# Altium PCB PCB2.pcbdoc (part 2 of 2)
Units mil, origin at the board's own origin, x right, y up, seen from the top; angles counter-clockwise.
Board outline 1825.45 x 2756.54 mil, 4 copper layers (Top Layer, 3.3V, GND, Bottom Layer); 87 components, 95 nets, 418 pads, 113 vias.
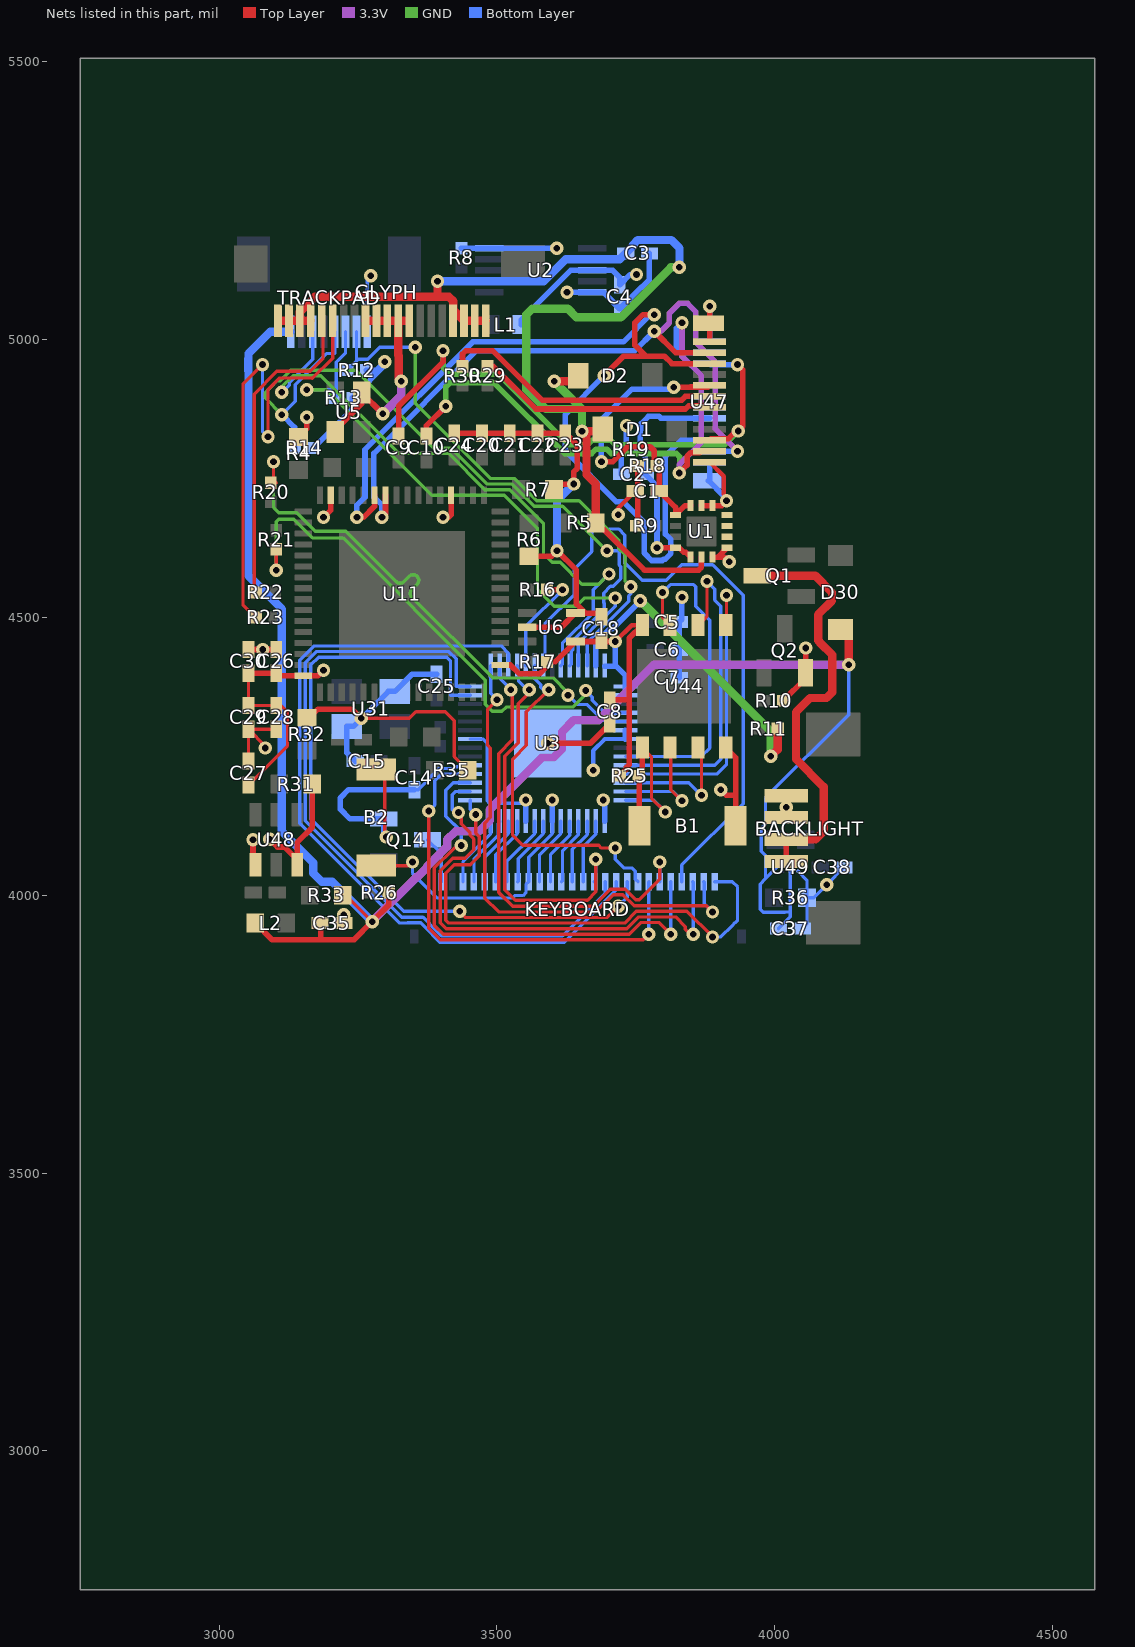
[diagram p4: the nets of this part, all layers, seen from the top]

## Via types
v1: diameter 24.02, hole 12.01, Top Layer to Bottom Layer, 113 vias

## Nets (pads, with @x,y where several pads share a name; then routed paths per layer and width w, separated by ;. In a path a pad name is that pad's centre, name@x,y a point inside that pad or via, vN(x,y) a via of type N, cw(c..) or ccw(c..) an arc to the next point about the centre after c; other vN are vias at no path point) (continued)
+3.3V: C4.2 C8.1 C18.1 C26.2 C27.2 C28.2 C29.2 C30.2 L1.2 R12.1 R13.1 R14.1 R16.2 R17.2 R25.1 R31.2 U1.3 U1.4 U2.8 U3.1 U3.10 U3.22 U3.33 U3.42 U3.43 U3.44 U3.48 U3.49 U6.4 U11.16 U11.34 U11.52 U11.63 U44.8 U48.3 | length 2677.7
  Top Layer w6: C27.2@3053.15,4198.54 3123.15,4268.54 3123.15,4330 3111.69,4341.46 C28.2@3103.15,4341.46 C29.2@3053.15,4341.46 C30.2@3053.15,4399.35
  Top Layer w8: v1(3713.15,4456.68) 3742.61,4486.14 U44.8@3761.8,4486.14
  Top Layer w10: C30.2@3053.15,4399.35 C26.2@3103.15,4399.35 3107.49,4395.01 U11.16@3151.96,4395.01 3178.16,4395.01 v1(3188.15,4405) ; v1(3091.11,4100.99) 3105.25,4086.85 3118.17,4086.85 U48.3@3140.55,4064.47 ; U48.3@3140.55,4054.76 U48.3@3140.55,4064.47 ; R31.2@3167.81,4200 3167.81,4122.02 3140.55,4094.76 U48.3@3140.55,4064.47 ; v1(3188.15,4680) 3201.17,4693.02 U11.63@3201.17,4719.81 ; v1(3403.15,4680) 3413.15,4680 3417.7,4684.55 U11.52@3417.7,4719.81 ; U11.34@3506.29,4414.7 3524.11,4414.7 3540.42,4398.39 3576.53,4398.39 3590.19,4412.04 R17.2@3590.19,4420 3604.81,4420 U6.4@3641.49,4456.68 v1(3713.15,4456.68) ; R16.2@3590.19,4550 v1(3618.15,4550) ; C8.1@3703.15,4351.46 3737.05,4351.46 3738.15,4350.36 ; R25.1@3721.11,4215 3733.07,4226.96 3733.07,4230.18 3738.15,4235.26 3738.15,4350.36 ; U44.8@3761.8,4486.14 3738.15,4462.5 3738.15,4350.36 ; U1.3@3887.84,4608.64 3897.68,4608.64 ; U1.4@3914.51,4625.47 3897.68,4608.64 ; v1(3918.15,4600) 3909.51,4608.64 3897.68,4608.64
  Bottom Layer w6: U3.22@3451.81,4281.25 3474.36,4281.25 3482.45,4273.16 3482.45,4170 3486.69,4165.76 3546.43,4165.76 v1(3552.2,4171.53) ; U3.33@3552.2,4413.15 3552.2,4484.06 v1(3618.15,4550)
  Bottom Layer w8: v1(3673.15,4225) 3673.15,4260 3694.4,4281.25 U3.49@3731.33,4281.25
  Bottom Layer w10: R14.1@3170.19,4805 3240.19,4875 R13.1@3240.19,4895 ; R13.1@3245.54,4900.43 3298.15,4953.03 v1(3298.15,4960) 3283.15,4945 R12.1@3265.19,4945 ; L1.2@3543.73,5026.97 3543.73,5035.58 3632.76,5124.61 U2.8@3671.61,5124.61 3708.54,5124.61 3721.17,5111.98 C4.2@3721.17,5098.44 3739.71,5116.98 v1(3751.17,5116.98) ; U3.10@3552.2,4133.61 v1(3552.2,4171.53) ; v1(3691.61,4171.53) 3693.93,4169.21 U3.1@3693.93,4133.61 ; U3.42@3693.94,4412.44 3714.36,4412.44 ; v1(3713.15,4456.68) 3713.15,4413.65 3714.36,4412.44 ; U3.49@3731.33,4281.25 U3.48@3731.33,4297 ; U3.44@3731.33,4359.99 U3.43@3731.33,4375.74 3731.33,4395.47 3714.36,4412.44
+5V: C35.2 C37.2 D30.2 L2.1 R26.2 R33.1 TRACKPAD.8 U49.B1 U49.C2 | length 3501
  Top Layer w6: R33.1@3222.81,4000 3228.15,4000 v1(3275.65,3952.5)
  Top Layer w10: L2.1@3065.59,3950.01 3095.6,3920 3182.97,3920 ; C35.2@3181.69,3950 3182.97,3948.71 3182.97,3920 ; R26.2@3305.19,4005 3305.19,3982.04 v1(3275.65,3952.5) 3243.15,3920 3182.97,3920
  Top Layer w15: D30.2@4118.15,4478.37 4133.15,4463.37 v1(4133.15,4415)
  3.3V w15: v1(3275.65,3952.5) 3357.66,4034.51 3358.71,4034.51 3373.64,4049.44 3373.64,4050.49 3410.67,4087.52 3410.67,4100.23 3425.6,4115.16 3467.71,4115.16 3487.21,4134.67 3487.21,4154.08 3581.02,4247.89 3602.14,4247.89 3617.07,4262.82 3617.07,4293.92 3638.15,4315 3683.15,4315 3783.15,4415 v1(4133.15,4415)
  Bottom Layer w6: C37.2@4006.69,3940 4028.15,3961.46 4028.15,3969.77 ; U49.C2@4014.37,4056.89 4012.92,4055.44 4009.26,4055.44 3983.29,4029.47 ; U49.B1@4028.15,4043.11 4028.15,3969.77 ; v1(4133.15,4415) 4133.15,4325 3983.29,4175.15 3983.29,4128.18 3975.86,4120.74 3975.86,4079.28 3983.29,4071.84 3983.29,4029.47 ; 3983.29,4029.47 3973.87,4020.05 3973.87,3974.89 3979.13,3969.62 4018.32,3969.62 4018.47,3969.77 4028.15,3969.77
  Bottom Layer w15: TRACKPAD.8@3128.56,5013.98 3092.13,5013.98 3053.15,4975 3053.15,4966.05 3052.66,4965.56 3052.66,4944.44 3053.15,4943.95 3053.15,4575 3113.15,4515 3113.15,4115 3169.67,4058.48 3169.67,4039.41 3184.6,4024.48 3203.67,4024.48 v1(3275.65,3952.5)
BACKLIGHT+: BACKLIGHT.3 BACKLIGHT.4 Q1.3 | length 775.8
  Top Layer w10: BACKLIGHT.4@4020.83,4060.95 BACKLIGHT.3@4020.83,4100.32
  Top Layer w15: Q1.3@3968.78,4575 4073.15,4575 4103.15,4545 4103.15,4530 4078.15,4505 4078.15,4458.45 4081.04,4455.56 4081.04,4455.07 4103.75,4432.35 4103.75,4365.61 4093.15,4355 4063.53,4355 4038.15,4329.62 4038.15,4245 4088.15,4195 4088.15,4115 4073.47,4100.32 BACKLIGHT.3@4020.83,4100.32
CAPS-: KEYBOARD.26 Q14.3 | length 86
  Bottom Layer w6: Q14.3@3375.12,4100 3399.69,4075.43 KEYBOARD.26@3399.69,4024.22
CC1: C1.2 R18.2 U1.10 U1.11 U47.A5 | length 570.2
  Top Layer w10: v1(3688.15,4780) 3708.15,4780 3735.22,4807.07 3776.08,4807.07 3783.15,4800 3783.15,4777.04 R18.2@3787.69,4772.5 3792.11,4768.08 C1.2@3792.11,4727.5 3821.79,4697.82 U1.11@3821.79,4684.53 3838.62,4701.36 U1.10@3848.47,4701.36 ; v1(3818.15,4914.09) 3848.12,4914.09 3848.66,4914.63 3879.94,4914.63 U47.A5@3882.73,4917.43
  Bottom Layer w10: v1(3688.15,4780) 3688.15,4855.8 3743.15,4910.8 3814.85,4910.8 v1(3818.15,4914.09)
CC2: C2.1 R19.2 U1.1 U1.14 U47.B5 | length 433.7
  Top Layer w10: v1(3788.15,4625.47) 3828.01,4625.47 3836.53,4616.95 3840.16,4616.95 U1.1@3848.47,4608.64
  Bottom Layer w10: v1(3788.15,4625.47) 3788.15,4736.46 C2.1@3767.11,4757.5 3767.11,4793.08 R19.2@3757.69,4802.5 3757.69,4836.19 3759.19,4837.69 3759.19,4848.18 3772.66,4861.65 3791.71,4861.65 3794.98,4858.38 U47.B5@3882.73,4858.38
EINK_OLED_USB_M: GLYPH.15 R23.1 | length 906.2
  Top Layer w6: R23.1@3066.11,4500 3043.15,4522.96 3043.15,4920 v1(3078.15,4955) ; v1(3088.15,4825) 3088.15,4910 3109.14,4930.99 3166.84,4930.99 3167.84,4930 3168.15,4930 3204.57,4966.42 GLYPH.15@3204.57,5033.82
  Bottom Layer w6: v1(3078.15,4955) 3078.15,4835 v1(3088.15,4825)
EINK_OLED_USB_P: GLYPH.16 R22.1 | length 577.5
  Top Layer w6: R22.1@3066.11,4545 3063.15,4547.96 3063.15,4901.97 3104.17,4942.99 3164.17,4942.99 3187.16,4965.99 3187.16,5031.55 GLYPH.16@3184.89,5033.82
GND: B1.1 B2.2 BACKLIGHT.1 BACKLIGHT.2 C1.1 C2.2 C3.2 C4.1 C5.2 C6.2 C7.2 C8.2 C14.1 C15.1 C18.2 C20.1 C21.1 C22.1 C23.1 C24.1 C25.2 C26.1 C27.1 C28.1 C29.1 C30.1 C35.1 C37.1 C38.2 GLYPH.8 GLYPH.9 GLYPH.10 GLYPH.11 GLYPH.12 Q2.2 Q14.2 R4.1 R6.2 R7.1 R8.1 R9.2 R10.1 R18.1 R19.1 R32.1 R35.2 R36.1 TRACKPAD.1 U1.8 U1.9 U2.5 U2.10 U3.19 U3.57 U5.2 U5.4 U6.2 U6.5 U31.2 U31.4 U44.4 U47.25 U47.26 U47.A1 U47.A12 U47.B1 U47.B12 U48.1 U49.A1 | length 4613.1
  Top Layer w6: C27.1@3053.15,4241.46 C29.1@3053.15,4298.54 ; v1(3083.15,4265) 3083.15,4268.54 C29.1@3053.15,4298.54 ; C28.1@3103.15,4298.54 C29.1@3053.15,4298.54 ; C35.1@3224.61,3950 v1(3224.61,3965) ; v1(3256.24,4318.33) 3342.65,4318.33 3354.34,4330.02 3407.3,4330.02 3423.16,4314.15 3423.16,4249.64 R35.2@3447.81,4225 ; B2.2@3299.63,4230.3 3298.15,4228.82 3298.15,4107.6 v1(3300.75,4105)
  Top Layer w8: v1(3718.15,4685) 3718.15,4696.46 C1.1@3749.19,4727.5 ; U47.A12@3882.73,4779.64 3908.26,4754.11 3908.26,4724.52 ccw(c3924.07,4724.52) 3913.15,4713.08 v1(3913.15,4710)
  Top Layer w10: C30.1@3053.15,4442.27 v1(3078.63,4442.27) C26.1@3103.15,4442.27 ; v1(3061.14,4100) 3061.14,4059.37 U48.1@3065.75,4054.76 ; R4.1@3143.15,4824.66 3158.15,4839.66 v1(3158.15,4860) ; R32.1@3158.15,4319.66 3162.81,4319.66 3178.15,4335 3239.57,4335 v1(3256.24,4318.33) ; U5.4@3209.42,4833.57 3209.42,4837.3 3256.66,4884.54 U5.2@3256.66,4904.43 v1(3294.62,4866.47) ; C24.1@3423.15,4831.46 C20.1@3473.15,4831.46 C21.1@3523.15,4831.46 C22.1@3573.15,4831.46 C23.1@3623.15,4831.46 3644.76,4809.85 3644.76,4768.44 3638.15,4761.82 v1(3638.15,4740) 3612.81,4740 R7.1@3602.81,4730 ; U6.2@3554.87,4482.27 3615.9,4482.27 U6.5@3641.49,4507.86 3659.43,4507.86 ; R6.2@3558.15,4610.34 3598.49,4610.34 v1(3608.15,4620) 3643.15,4585 3643.15,4524.15 3659.43,4507.86 ; v1(3591.58,4273.38) 3667.99,4273.38 C8.2@3703.15,4308.54 ; C18.2@3688.15,4501.46 3681.74,4507.86 3659.43,4507.86 ; R9.2@3751.11,4665 3753.61,4667.5 R18.1@3753.61,4772.5 ; U1.9@3868.15,4701.36 U1.8@3887.84,4701.36 3904.51,4701.36 v1(3913.15,4710) ; U47.A1@3882.7,4996.14 3882.7,5027.64 3880.73,5029.61 3883.15,5032.02 v1(3883.15,5060) ; v1(3903.15,4190) 3913.15,4180 3929.76,4180 ; U44.4@3911.8,4265.65 3929.76,4247.69 3929.76,4180 ; B1.1@3929.76,4125 3929.76,4180 ; R10.1@4015.19,4350 4055.55,4390.36 Q2.2@4055.55,4400.63 v1(4055.55,4445) ; BACKLIGHT.2@4020.83,4139.69 v1(4020.83,4158.21) BACKLIGHT.1@4020.83,4179.06
  Top Layer w15: GLYPH.12@3264.31,5033.82 GLYPH.11@3283.31,5033.82 GLYPH.10@3303,5033.82 GLYPH.9@3322.68,5033.82 ; v1(3328.15,4925) 3323.64,4929.51 3323.64,4970.56 3322.68,4971.52 GLYPH.9@3322.68,5033.82 ; GLYPH.8@3341.67,5033.82 GLYPH.9@3322.68,5033.82
  3.3V w15: v1(3294.62,4866.47) 3328.15,4900 v1(3328.15,4925)
  Bottom Layer w6: TRACKPAD.1@3267.05,5013.98 3267.05,5108.9 v1(3273.15,5115) ; C14.1@3351.61,4190.07 3358.24,4190.07 3396.44,4228.28 3423.53,4228.28 3426.44,4231.18 3448.99,4231.18 U3.19@3451.81,4234.01 ; U49.A1@4041.93,4043.11 4058.05,4026.99 R36.1@4058.05,3995.62 ; C37.1@4049.61,3940 4058.05,3948.44 R36.1@4058.05,3995.62 ; C38.2@4124.61,4050 v1(4093.43,4018.82) 4070.22,3995.62 R36.1@4058.05,3995.62
  Bottom Layer w10: C15.1@3245.15,4241.53 3229.92,4256.77 U31.2@3229.92,4303.81 3241.73,4303.81 v1(3256.24,4318.33) 3304.72,4366.8 U31.4@3316.53,4366.8 3347.72,4397.99 C25.2@3391.61,4397.99 ; v1(3300.75,4105) 3296.38,4109.37 Q14.2@3296.38,4137.4 3235.75,4137.4 3218.15,4155 3218.15,4175 3233.22,4190.07 C14.1@3351.61,4190.07 ; R8.1@3436.17,5164.02 3486.53,5164.02 3486.99,5164.41 v1(3607.72,5164.41) ; v1(3626.17,5085.23) U2.10@3671.61,5085.23 3691.46,5085.23 C4.1@3721.17,5055.52 3759.64,5093.99 3760.69,5093.99 3774.61,5107.9 C3.2@3774.61,5155 ; C2.2@3724.19,4757.5 3724.19,4801.92 R19.1@3723.61,4802.5 3733.15,4812.04 v1(3733.15,4845) ; C7.2@3828.07,4391.53 C6.2@3828.07,4441.53 C5.2@3828.07,4491.53 3833.07,4496.53 v1(3833.07,4536.53) ; U47.B1@3882.73,4779.64 3882.7,4748.11 3880.73,4746.14 3908.31,4718.56 ccw(c3924.04,4724.49) 3913.15,4711.68 v1(3913.15,4710) ; U47.B12@3882.7,4996.14 3882.7,5026.49 3882.7,5059.55 v1(3883.15,5060)
  Bottom Layer w15: v1(3608.15,4620) 3608.15,4710 v1(3638.15,4740)
INT_USBC_CTRL: U1.5
KBRD0: KEYBOARD.1 U3.15 | length 937.3
  Top Layer w6: v1(3461.72,4145.22) 3461.72,4111.96 3468.16,4105.51 3468.16,4070.85 3452.3,4054.98 3423.15,4055 3408.15,4040 3408.15,3955 3413.15,3950 3729.84,3950.02 3750.84,3971.02 3842.12,3971.02 v1(3888.15,3925)
  Bottom Layer w6: U3.15@3451.81,4171.02 3452.03,4170.81 3452.03,4154.91 v1(3461.72,4145.22) ; v1(3888.15,3925) 3903.15,3925 3923.18,3945.03 3923.18,3945.26 3928.45,3950.52 3928.67,3950.52 3933.15,3955 3933.15,4015 3923.94,4024.21 KEYBOARD.1@3891.81,4024.21
KBRD1: KEYBOARD.2 U3.29 | length 942.9
  Top Layer w6: v1(3500.26,4352.1) 3483.15,4334.99 3483.15,4270 3488.15,4265 3488.15,4140 3478.15,4130 3478.15,3995 3503.15,3970 3678.15,3970 3709.14,4000.99 3726.84,4000.99 3746.8,3981.04 3877.11,3981.04 v1(3888.15,3970)
  Bottom Layer w6: U3.29@3489.2,4413.15 3489.2,4363.16 v1(3500.26,4352.1) ; KEYBOARD.2@3872.13,4024.21 3873.15,4023.19 3873.15,3985 v1(3888.15,3970)
KBRD2: KEYBOARD.3 U3.16 | length 902.8
  Top Layer w6: v1(3431.04,4149.01) 3436.04,4144.01 3436.04,4128.47 3451.7,4112.81 3451.7,4107.81 3458.15,4101.37 3458.15,4081.97 3442.98,4066.81 3420.79,4066.81 3398.13,4044.15 3398.13,3950.85 3409,3939.98 3733.97,3939.98 3754.99,3961.01 3821.83,3961.01 3839.14,3943.7 3839.14,3939.01 3846.41,3931.74 3851.41,3931.74 v1(3853.15,3930)
  Bottom Layer w6: v1(3431.04,4149.01) 3428.57,4146.54 3426.61,4146.54 3419.64,4153.51 3419.64,4180.76 3425.64,4186.76 U3.16@3451.81,4186.76 ; KEYBOARD.3@3852.44,4024.21 3853.15,4023.5 v1(3853.15,3930)
KBRD3: KEYBOARD.4 U3.35 | length 1215.3
  Bottom Layer w6: U3.35@3583.69,4413.15 3586.52,4415.98 3586.52,4488.37 3639.14,4540.99 3639.14,4586.99 3670.64,4618.49 3670.64,4655 3674.88,4659.24 3718.91,4659.24 3730.13,4648.02 3730.13,4598.4 3761.54,4566.98 3804.75,4566.98 3832.77,4595 3888.15,4595 3943.15,4540 3943.15,4165 3832.76,4054.61 KEYBOARD.4@3832.76,4024.21
KBRD4: KEYBOARD.5 U3.17 | length 873.8
  Top Layer w6: v1(3436.16,4089.67) 3431.49,4085 3423.01,4085 3387.53,4049.52 3387.53,3945.62 3403.13,3930.02 3738.16,3930.02 3759.14,3950.99 3792.16,3950.99 v1(3813.15,3930)
  Bottom Layer w6: v1(3436.16,4089.67) 3436.16,4115 3423.15,4128.02 3422.34,4128.02 3408.15,4142.21 3408.15,4189.43 3421.23,4202.51 U3.17@3451.81,4202.51 ; KEYBOARD.5@3813.07,4024.21 3813.07,3930.08 v1(3813.15,3930)
KBRD5: KEYBOARD.6 U3.30 | length 831
  Top Layer w6: v1(3524.78,4370.01) 3527.61,4367.19 3527.61,4279.46 3503.15,4255 3503.15,4005 3528.15,3980 3673.15,3980 3704.16,4011.01 3730.99,4011.01 3750.07,3991.93 3756.07,3991.93 3793.15,4029 v1(3793.15,4060)
  Bottom Layer w6: U3.30@3504.95,4413.15 3504.95,4390.61 3524.78,4370.78 v1(3524.78,4370.01) ; v1(3793.15,4060) 3793.39,4059.76 KEYBOARD.6@3793.39,4024.21
KBRD6: KEYBOARD.7 U3.18 | length 841.2
  Top Layer w6: v1(3377.51,4151.77) 3377.51,3940.63 3398.15,3920 3763.15,3920 v1(3773.15,3930)
  Bottom Layer w6: v1(3377.51,4151.77) 3388.15,4162.41 3388.15,4205.82 3400.59,4218.26 U3.18@3451.81,4218.26 ; v1(3773.15,3930) 3773.15,4023.66 KEYBOARD.7@3773.7,4024.21
KBRD7: KEYBOARD.8 U3.34 | length 628.7
  Top Layer w6: v1(3593.15,4370) 3553.15,4330 3553.15,4270 3528.15,4245 3528.15,4108.45 3546.6,4090 3683.15,4090 3688.15,4085 v1(3713.15,4085)
  Bottom Layer w6: U3.34@3567.94,4413.15 3567.94,4389.89 3579.14,4378.7 3579.14,4374.41 3583.55,4370 v1(3593.15,4370) ; v1(3713.15,4085) 3713.15,4065.08 3729.29,4048.94 3743.96,4048.94 3749.22,4043.68 3749.22,4029.01 KEYBOARD.8@3754.02,4024.21
KBRD8: KEYBOARD.9 U3.27 | length 1319.4
  Top Layer w6: v1(3433.15,3971.01) 3444.16,3960 3698.15,3960 v1(3718.15,3980)
  Bottom Layer w6: v1(3433.15,3971.01) 3332.14,3971.01 3165.16,4137.99 3165.16,4414.52 3179.24,4428.6 3409.54,4428.6 3416.61,4421.53 3416.61,4359.99 U3.27@3451.81,4359.99 ; v1(3718.15,3980) 3734.33,3996.18 KEYBOARD.9@3734.33,4024.21
KBRD9: KEYBOARD.10 U3.31 | length 1420.2
  Bottom Layer w6: U3.31@3520.7,4413.15 3520.7,4435.7 3507.77,4448.64 3170.94,4448.64 3145.12,4422.82 3145.12,4129.69 3324.82,3950 3339.34,3950 3339.87,3950.52 3363.06,3950.52 3368.32,3945.26 3368.32,3945 3398.32,3915 3620.11,3915 3714.65,4009.54 KEYBOARD.10@3714.65,4024.21
KBRD10: KEYBOARD.11 U3.28 | length 1322.6
  Bottom Layer w6: U3.28@3451.81,4375.74 3426.82,4375.74 3426.63,4375.93 3426.63,4425.68 3413.69,4438.62 3175.09,4438.62 3155.14,4418.67 3155.14,4133.84 3328.42,3960.56 3367.18,3960.56 3378.34,3949.41 3378.34,3949.15 3400.32,3927.17 3618.11,3927.17 3694.96,4004.02 KEYBOARD.11@3694.96,4024.21
KBRD11: KEYBOARD.12 U3.32 | length 711.4
  Top Layer w6: v1(3558.15,4370) 3558.15,4364.53 3538.62,4345 3538.62,4274.46 3514.16,4250 3514.16,4010.29 3533.44,3991.02 3663.15,3991.02 3678.15,4006.02 v1(3678.15,4065)
  Bottom Layer w6: U3.32@3536.45,4413.15 3538.81,4410.79 3538.81,4385.67 3554.48,4370 v1(3558.15,4370) ; KEYBOARD.12@3675.26,4024.22 3678.15,4027.11 v1(3678.15,4065)
KBRD12: KEYBOARD.13 U3.2 | length 118.8
  Bottom Layer w6: KEYBOARD.13@3655.59,4024.22 3655.59,4087.44 3678.18,4110.04 U3.2@3678.18,4133.61
KBRD13: KEYBOARD.14 U3.3 | length 120.4
  Bottom Layer w6: KEYBOARD.14@3635.91,4024.22 3635.91,4082.76 3662.43,4109.29 U3.3@3662.43,4133.61
KBRD14: KEYBOARD.15 U3.4 | length 122
  Bottom Layer w6: KEYBOARD.15@3616.22,4024.22 3618.15,4026.15 3618.15,4080 3646.68,4108.54 U3.4@3646.68,4133.61
KBRD15: KEYBOARD.16 U3.5 | length 123.6
  Bottom Layer w6: KEYBOARD.16@3596.54,4024.22 3596.54,4073.39 3630.94,4107.8 U3.5@3630.94,4133.61
KBRD16: KEYBOARD.17 U3.6 | length 125.3
  Bottom Layer w6: KEYBOARD.17@3576.85,4024.22 3576.85,4072.72 3615.19,4111.07 U3.6@3615.19,4133.61
KBRD17: KEYBOARD.20 U3.9 | length 130.2
  Bottom Layer w6: KEYBOARD.20@3517.8,4024.22 3517.8,4060.91 3567.94,4111.06 U3.9@3567.94,4133.61
KBRD18: KEYBOARD.19 U3.8 | length 128.5
  Bottom Layer w6: KEYBOARD.19@3537.48,4024.22 3538.43,4025.17 3538.43,4065.8 3583.69,4111.07 U3.8@3583.69,4133.61
KBRD19: B2.1 KEYBOARD.18 U3.7 | length 500.9
  Top Layer w6: B2.1@3283.15,4053.39 3341.54,4053.39 v1(3348.15,4060)
  Bottom Layer w6: v1(3348.15,4060) 3348.15,4040 3393.15,3995 3527.95,3995 3532.44,3999.49 3547.11,3999.49 3552.37,4004.75 3552.37,4019.42 KEYBOARD.18@3557.17,4024.22 3557.17,4068.79 3599.44,4111.07 U3.7@3599.44,4133.61
  Bottom Layer w10: U3.7@3599.44,4133.61 v1(3599.44,4171.53)
KBRD20: KEYBOARD.21 U3.11 | length 125.3
  Bottom Layer w6: KEYBOARD.21@3498.11,4024.22 3498.11,4072.72 3536.45,4111.07 U3.11@3536.45,4133.61
KBRD21: KEYBOARD.22 U3.12 | length 126.9
  Bottom Layer w6: KEYBOARD.22@3478.43,4024.22 3478.43,4068.79 3520.7,4111.07 U3.12@3520.7,4133.61
KBRD22: KEYBOARD.23 U3.13 | length 128.5
  Bottom Layer w6: KEYBOARD.23@3458.74,4024.22 3458.74,4064.85 3502.12,4108.24 3502.12,4128.98 3504.95,4131.81 U3.13@3504.95,4133.61
KBRD23: KEYBOARD.24 U3.14 | length 130.2
  Bottom Layer w6: KEYBOARD.24@3439.06,4024.22 3439.06,4060.91 3489.2,4111.06 U3.14@3489.2,4133.61
KBRD_CTRL: R11.1 U3.41 | length 584.8
  Top Layer w15: v1(3993.15,4250) 4005.19,4262.04 R11.1@4005.19,4300
  GND w15: v1(3758.15,4530) 3993.15,4295 v1(3993.15,4250)
  Bottom Layer w10: U3.41@3678.18,4413.15 3678.18,4450.04 3690.16,4462.01 3690.16,4466.21 3703.62,4479.68 3707.82,4479.68 v1(3758.15,4530)
KBRDUSB_M: R21.1 U3.46 | length 964.6
  Top Layer w6: v1(3103.15,4585) R21.1@3103.15,4622.96
  GND w6: v1(3103.15,4585) 3103.15,4672.26 3107.39,4676.5 3134.68,4676.5 3168.18,4643 3223.18,4643 3479.27,4386.91 3479.27,4343.41 3491.57,4331.11 3508.96,4331.11 3516.65,4338.8 3636.64,4338.8 3659.86,4362.03 v1(3659.86,4368.51)
  Bottom Layer w6: v1(3659.86,4368.51) 3671.89,4356.48 3671.89,4350.54 3695.81,4326.63 3701.81,4326.63 3703.68,4328.5 U3.46@3731.33,4328.5
KBRDUSB_P: R20.1 U3.47 | length 967.6
  Top Layer w6: v1(3098.15,4780) 3098.15,4747.04 R20.1@3103.15,4742.04
  GND w6: v1(3098.15,4780) 3098.15,4697.74 3107.39,4688.5 3139.65,4688.5 3173.15,4655 3228.15,4655 3318.71,4564.44 ccw(c3325.78,4571.51) 3332.85,4564.44 3342.35,4573.93 cw(c3349.42,4566.86) 3356.49,4559.79 3347,4550.29 ccw(c3354.07,4543.22) 3347,4536.15 3492.14,4391.01 3601.83,4391.01 3627.94,4364.89 v1(3627.94,4359.79)
  Bottom Layer w6: v1(3627.94,4359.79) 3644.34,4343.39 3662.07,4343.39 3690.83,4314.63 3701.81,4314.63 3703.68,4312.75 U3.47@3731.33,4312.75
QSPI_SCLK: U3.52 U44.6 | length 592.3
  Top Layer w6: U44.6@3861.8,4486.14 3878.15,4502.5 v1(3878.15,4565)
  Bottom Layer w6: U3.52@3731.33,4234.01 3892.16,4234.01 3903.15,4245 3903.13,4520.33 3892.16,4531.3 3892.16,4550.99 v1(3878.15,4565)
QSPI_SD0: U3.53 U44.5 | length 548.2
  Top Layer w6: U44.5@3911.8,4486.14 3913.15,4487.5 v1(3913.15,4540)
  Bottom Layer w6: U3.53@3731.33,4218.26 3896.41,4218.26 3913.15,4235 v1(3913.15,4540)
QSPI_SD1: U3.55 U44.2 | length 213.3
  Top Layer w6: U44.2@3811.8,4265.65 3813.15,4264.3 3813.15,4190 v1(3833.15,4170)
  Bottom Layer w6: U3.55@3731.33,4186.76 3816.39,4186.76 v1(3833.15,4170)
QSPI_SD2: U3.54 U44.3 | length 234.4
  Top Layer w6: U44.3@3861.8,4265.65 3868.15,4259.3 v1(3868.15,4180)
  Bottom Layer w6: U3.54@3731.33,4202.51 3845.64,4202.51 v1(3868.15,4180)
QSPI_SD3: U3.51 U44.7 | length 590.6
  Top Layer w6: v1(3798.15,4545) 3798.15,4499.79 U44.7@3811.8,4486.14
  Bottom Layer w6: U3.51@3731.33,4249.76 3867.91,4249.76 3883.15,4265 3883.15,4495 3858.15,4520 3858.15,4555 3853.91,4559.24 3812.39,4559.24 v1(3798.15,4545)
QSPI_SS: B1.2 R25.2 U3.56 U44.1 | length 357.3
  Top Layer w6: U44.1@3761.8,4265.65 3778.15,4249.3 3778.15,4175 v1(3803.15,4150)
  Top Layer w10: B1.2@3756.54,4125 3756.54,4213.65 R25.2@3755.19,4215 3761.8,4221.61 U44.1@3761.8,4265.65
  Bottom Layer w6: U3.56@3731.33,4171.02 3782.13,4171.02 v1(3803.15,4150)
SCL_USBC_CTRL: U1.6
SDA_USBC_CTRL: U1.7
SSRXN1: U11.59 U47.A3 U47.B3 | length 1871.7
  Top Layer w10: v1(3248.15,4680) 3259.91,4680 3279.91,4700 U11.59@3279.91,4719.81 ; v1(3693.15,4935) 3728.15,4970 3768.15,4970 ; v1(3783.15,5044.95) 3763.1,5044.95 3748.15,5030 3748.15,4990 3768.15,4970 ; U47.A3@3882.73,4956.8 3814.86,4956.8 3801.65,4970 3768.15,4970
  Bottom Layer w10: v1(3248.15,4680) 3248.15,4702.01 3262.65,4716.51 3262.65,4801.98 3456.66,4996 3727.57,4996 3776.52,5044.95 v1(3783.15,5044.95) ; v1(3693.15,4935) 3623.15,4865 3623.15,4800 3715.16,4707.99 3727.67,4707.99 3765.16,4670.51 3765.16,4615.95 3778.62,4602.48 3797.67,4602.48 3800.19,4605 3803.15,4605 3813.15,4615 3813.15,4640 3803.15,4650 3803.15,4790 3832.15,4819.01 U47.B3@3882.73,4819.01
SSRXP1: U11.58 U47.A2 U47.B2 | length 1318.9
  Top Layer w10: v1(3293.15,4680) 3299.59,4686.44 U11.58@3299.59,4719.81 ; v1(3783.15,5014.95) 3821.61,4976.48 U47.A2@3882.73,4976.48
  3.3V w10: v1(3783.15,5014.95) 3795.1,5014.95 3810.16,5030 3810.16,5047.01 3828.15,5065 3843.15,5065 3858.15,5050 3858.15,4995 3893.15,4960 3893.15,4839.31 v1(3933.15,4799.31)
  Bottom Layer w10: v1(3293.15,4680) 3293.15,4702.01 3278.65,4716.51 3278.65,4795.36 3463.29,4980 3748.2,4980 v1(3783.15,5014.95) ; U47.B2@3882.73,4799.31 v1(3933.15,4799.31)
SSTXN1: C9.1 U47.A10 U47.B10 | length 1059
  Top Layer w10: C9.1@3323.15,4826.46 3323.15,4880 3403.15,4960 v1(3403.15,4980) ; U47.A10@3882.73,4819.01 3885.52,4821.8 3916.81,4821.8 3930.43,4835.42 v1(3934.52,4835.42) 3942.69,4843.59 3942.69,4945.46 v1(3933.15,4955)
  GND w10: v1(3403.15,4980) 3403.15,4950.07 3415.22,4938 3501.79,4938 3628.79,4811 3664,4811 3672,4818.99 3704.3,4818.99 3712.29,4811 3910.1,4811 v1(3934.52,4835.42)
  Bottom Layer w10: U47.B10@3882.73,4956.8 3884.53,4955 v1(3933.15,4955)
SSTXP1: C10.1 U47.A11 U47.B11 | length 1111.5
  Top Layer w10: C10.1@3373.15,4826.46 3373.15,4845 v1(3408.15,4880) ; v1(3828.15,4760) 3842.22,4774.07 3842.22,4790.09 3848.66,4796.52 3864.67,4796.52 3867.46,4799.31 U47.A11@3882.73,4799.31
  3.3V w10: v1(3828.15,4760) 3828.15,4775 3868.15,4815 3868.15,4935 3833.15,4970 v1(3833.15,5030)
  GND w10: v1(3408.15,4880) 3408.15,4914.93 3415.22,4922 3495.16,4922 3622.16,4795 3670.63,4795 3678.62,4802.99 3697.67,4802.99 3705.66,4795 3823.15,4795 3829.01,4789.14 3829.01,4760.86 v1(3828.15,4760)
  Bottom Layer w10: v1(3833.15,5030) 3823.15,5020 3823.15,4985 3831.66,4976.48 U47.B11@3882.73,4976.48
TOUCHPAD_ID: TRACKPAD.6 U3.37 | length 1139.5
  GND w6: v1(3113.15,4905) 3113.15,4915 3133.15,4935 3183.15,4935 3323.15,4795 3413.15,4795 3478.15,4730 3523.15,4730 3583.91,4669.24 3583.91,4614.24 3588.15,4610 3588.46,4610 3599.45,4599.01 3614.14,4599.01 3653.15,4560 3683.46,4560 v1(3701.71,4578.24)
  Bottom Layer w6: v1(3113.15,4905) 3126.09,4917.94 3126.09,4922.11 3168.62,4964.63 TRACKPAD.6@3168.62,5013.98 ; U3.37@3615.19,4413.15 3618.02,4415.98 3618.02,4453.56 3673.15,4508.68 3673.15,4549.69 v1(3701.71,4578.24) 3700.65,4579.3 v1@3700.65,4582.5
TOUCHPAD_INT: R12.2 TRACKPAD.2 U3.40 | length 1028.6
  GND w6: v1(3353.16,4986.3) 3353.16,4885.02 3488.15,4750.03 3531.45,4750.03 3571.46,4710.02 3647.82,4710.02 3719.14,4638.7 3719.14,4624.01 3730.65,4612.5 3730.65,4565 v1(3740.65,4555)
  Bottom Layer w6: R12.2@3231.11,4945 3245.07,4958.96 3245.07,4959.35 3250.33,4964.61 3267.45,4964.61 3272.84,4970 3273.15,4970 3289.45,4986.3 v1(3353.16,4986.3) ; 3247.36,4961.64 TRACKPAD.2@3247.36,5013.98 ; U3.40@3662.43,4413.15 3662.43,4455.48 3698.65,4491.69 3699.84,4491.69 3737.16,4529.01 3737.16,4538.7 3740.65,4542.19 v1(3740.65,4555)
TOUCHPAD_SCL: R13.2 TRACKPAD.3 U3.39 | length 1121.3
  GND w6: v1(3158.15,4910) 3193.15,4910 3383.15,4720 3513.15,4720 3573.15,4660 3573.15,4550 3603.15,4520 3643.15,4520 3658.15,4535 v1(3713.15,4535)
  Bottom Layer w6: v1(3158.15,4910) 3201.89,4910 3203.78,4908.11 ; R13.2@3206.11,4895 3210.99,4899.88 3210.99,4900.9 3210.99,4959.35 3227.68,4976.04 TRACKPAD.3@3227.68,5013.98 ; U3.39@3646.68,4413.15 3646.68,4453.89 3694.5,4501.71 3694.85,4501.71 3713.15,4520 v1(3713.15,4535)
  Bottom Layer w10: 3203.78,4908.11 R13.2@3210.99,4900.9
TOUCHPAD_SDA: R14.2 TRACKPAD.4 U3.38 | length 1360.9
  GND w6: v1(3113.15,4865) 3083.15,4895 3083.15,4904.69 3104.45,4925.99 3109.98,4925.99 3129,4945.02 3245.78,4945 3385.76,4805.02 3417.3,4805.02 3482.3,4740.02 3527.3,4740.02 3567.31,4700 3618.15,4700 v1(3698.15,4620)
  Bottom Layer w6: v1(3113.15,4865) 3137.16,4889.01 3137.16,4918.7 3193.3,4974.84 3207.99,4974.84 TRACKPAD.4@3207.99,5013.98 ; U3.38@3630.94,4413.15 3633.76,4415.97 3633.76,4438.53 3636.67,4441.43 3636.67,4458.04 3693.15,4514.52 3693.15,4525.31 3692.16,4526.3 3692.16,4543.7 3704.45,4555.99 3709.14,4555.99 3723.15,4570 3723.15,4591.22 3720.12,4594.25 3720.12,4623.03 3717.09,4620 v1(3698.15,4620)
  Bottom Layer w10: v1(3113.15,4865) 3136.11,4842.04 R14.2@3136.11,4805
USB_UP+: R30.2 U47.A6 U47.B6 | length 435
  Top Layer w10: 3483.15,4952.04 3493.15,4952.04 3570.09,4875.1 3839.3,4875.1 3845.02,4880.83 3879.9,4880.83 3882.7,4878.03
USB_UP-: R29.2 U47.A7 U47.B7 | length 508.6
  Top Layer w10: 3438.15,4952.04 3438.15,4974 3444.15,4980 3492.49,4980 3581.39,4891.1 3832.67,4891.1 3839.29,4897.72 3882.7,4897.72
VBUS: C3.1 D1.1 D2.1 GLYPH.1 GLYPH.2 GLYPH.3 GLYPH.4 GLYPH.17 GLYPH.18 GLYPH.19 GLYPH.20 R5.1 U1.2 U2.2 U2.7 | length 2176.1
  Top Layer w10: R5.1@3677.81,4670 3680.66,4670 3765.66,4585 3863.15,4585 3868.15,4590 U1.2@3868.15,4608.64
  Top Layer w15: GLYPH.20@3106.15,5033.82 GLYPH.19@3125.83,5033.82 GLYPH.18@3145.52,5033.82 ; GLYPH.17@3164.51,5033.82 GLYPH.18@3145.52,5033.82 ; v1(3393.15,5104.92) 3393.15,5077.83 3394.15,5076.83 ; GLYPH.1@3480.16,5033.82 GLYPH.2@3460.48,5033.82 GLYPH.3@3440.79,5033.82 3421.79,5052.82 3421.79,5068.93 3413.89,5076.83 3394.15,5076.83 ; v1(3603.15,4925) 3636.52,4925 D2.1@3646.52,4935 ; R5.1@3677.81,4670 3678.15,4670.34 3678.15,4740 3661.28,4756.87 3661.28,4826.87 v1(3653.15,4835) 3686.76,4835 D1.1@3690.55,4838.79 ; GLYPH.18@3145.52,5033.82 3145.52,5049.94 3172.41,5076.83 3394.15,5076.83
  GND w15: v1(3603.15,4925) 3653.15,4875 ; v1(3653.15,4835) 3653.15,4875 ; v1(3828.15,5130) 3813.15,5130 3723.15,5040 3643.15,5040 3627.54,5055.61 3563.75,5055.61 3553.15,5045 3553.15,4910 3588.15,4875 3653.15,4875
  Bottom Layer w15: v1(3393.15,5104.92) U2.2@3486.57,5104.92 3584.29,5104.92 3623.67,5144.3 U2.7@3671.61,5144.3 3720.99,5144.3 C3.1@3731.69,5155 3745.57,5168.88 3745.57,5171.22 3753.47,5179.11 3814.03,5179.11 3828.75,5164.39 3828.75,5130.61 v1(3828.15,5130)
pads on no net: BACKLIGHT.5 BACKLIGHT.6 GLYPH.5 GLYPH.6 GLYPH.7 GLYPH.13 GLYPH.14 GLYPH.21 GLYPH.22 KEYBOARD.27 KEYBOARD.28 TRACKPAD.5 TRACKPAD.7 TRACKPAD.9 TRACKPAD.10 U1.15 U2.4 U2.6 U2.9 U3.24 U3.25 U11.3 U11.4 U11.6 U11.7 U11.11 U11.12 U11.14 U11.15 U11.17 U11.18 U11.19 U11.20 U11.22 U11.23 U11.24 U11.25 U11.26 U11.27 U11.29 U11.30 U11.32 U11.33 U11.35 U11.36 U11.39 U11.40 U11.41 U11.42 U11.43 U11.44 U11.45 U11.46 U11.47 U11.50 U11.60 U11.65 U44.9 U47.A8
copper on no net: | length 1080.8
  3.3V w6: 3146.96,4406.79 3193.27,4360.48 3433.15,4600.36 3433.15,4685.74 3411.95,4706.93 3154.57,4706.93 3146.96,4699.32 3146.96,4406.79

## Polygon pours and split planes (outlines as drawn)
+3.3V on 3.3V (solid, remove dead copper): 3018.15,5200 4168.15,5200 4168.15,3900 3018.15,3900
GND on GND (solid, remove dead copper): 3018.15,5200 4168.15,5200 4168.15,3900 3018.15,3900

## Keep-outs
Board Outline Layer:
  lines w5.98: 3961.51,3900 4168.15,3900 4168.15,4656.94 3964.15,4656.94
  lines w6: 3959.51,4724.52 3964.15,4724.52 3964.15,4656.94 ; 3959.5,5051.29 3959.5,5200 3018.15,5200 3018.15,3900 3961.51,3900

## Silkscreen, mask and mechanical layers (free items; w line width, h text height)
Top Silkscreen Layer:
  text "Thanks Arya!" at 3613.15,5125 h60
  text "Built and designed" at 3358.15,3955 h60
  text "with ♡ by JJ Shapiro" at 3363.15,3905 h60
Bottom Silkscreen Layer:
  text "And the universe said I love you... /  Because you are love." at 3173.15,4995 h70 r90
